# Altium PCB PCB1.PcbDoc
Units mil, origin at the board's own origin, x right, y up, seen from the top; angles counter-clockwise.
Board outline 2460.63 x 1000 mil, 4 copper layers (Top Layer, GND, POW, Bottom Layer), stack 30.634 mil thick; 99 components, 71 nets, 311 pads, 135 vias.
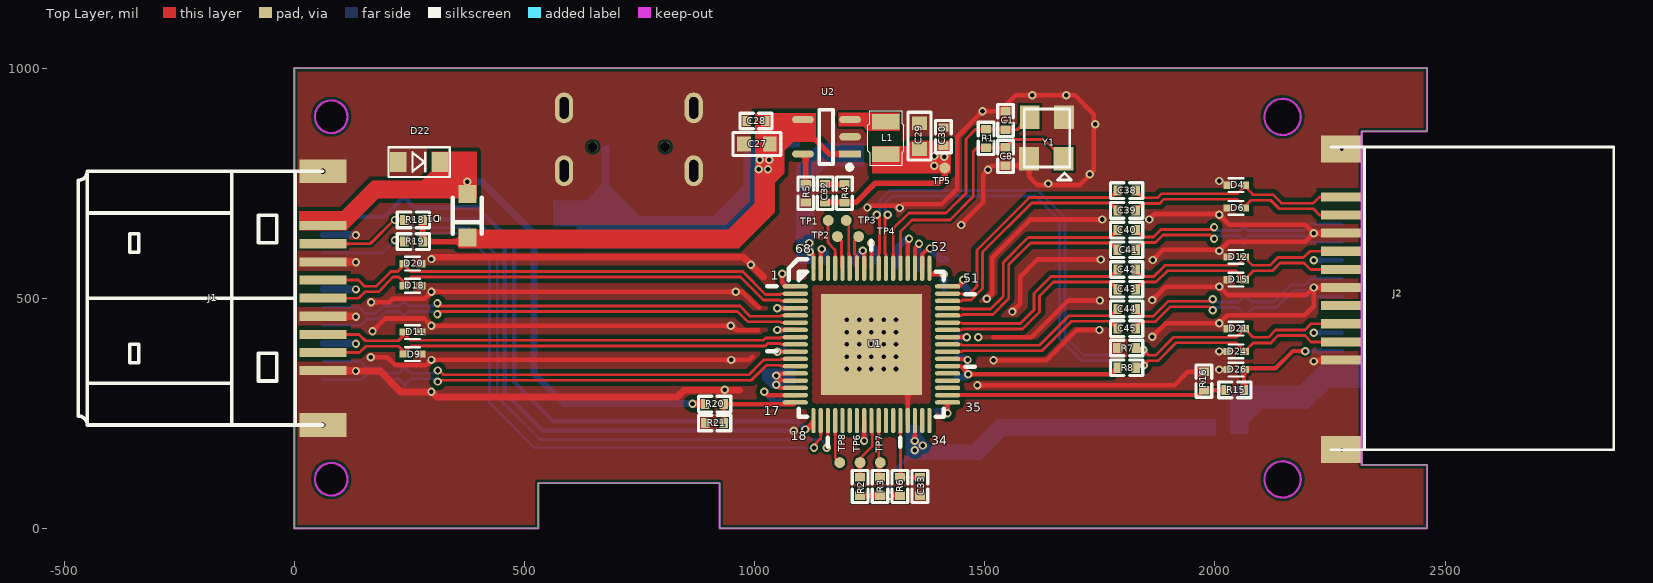
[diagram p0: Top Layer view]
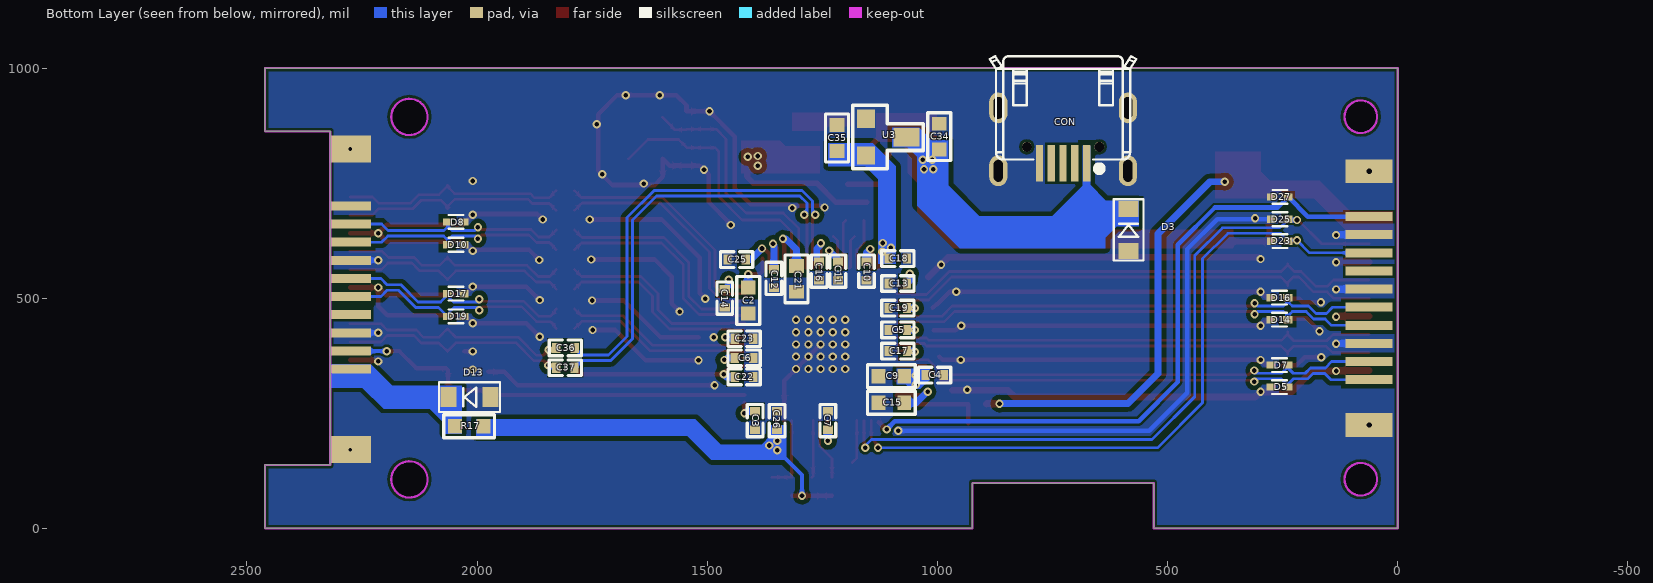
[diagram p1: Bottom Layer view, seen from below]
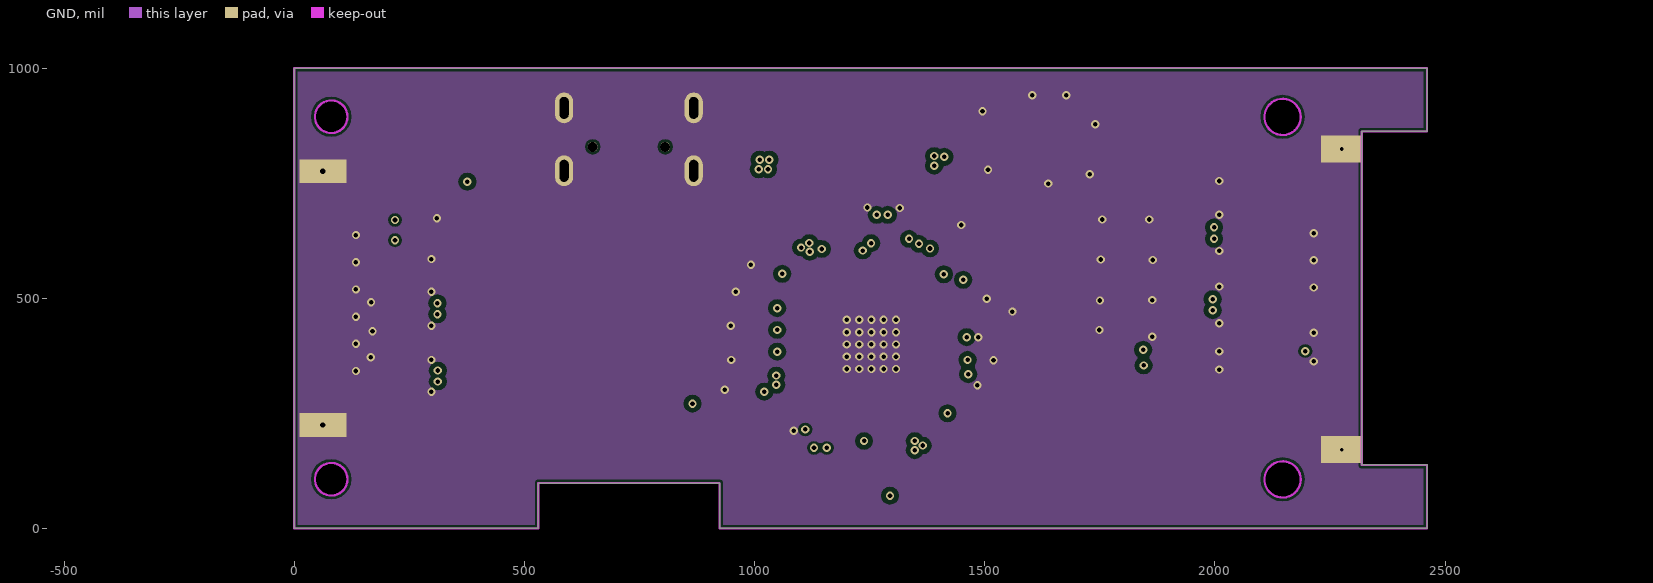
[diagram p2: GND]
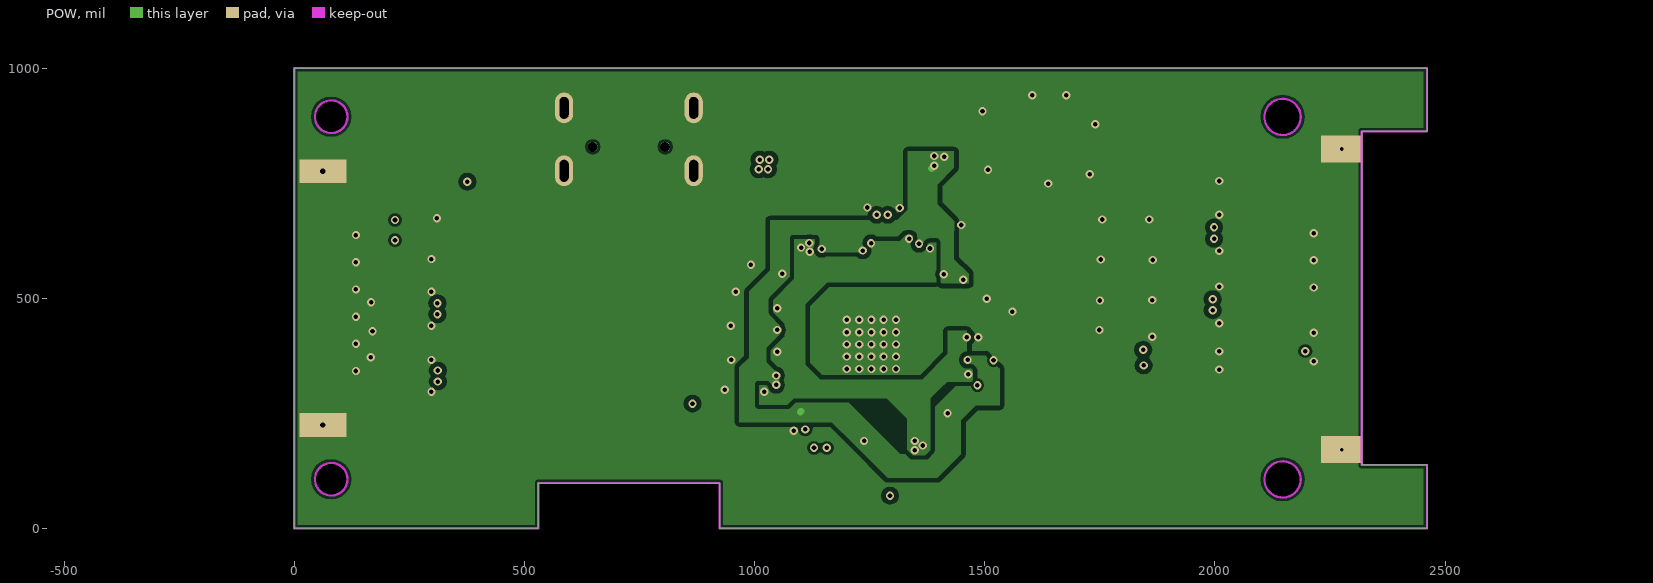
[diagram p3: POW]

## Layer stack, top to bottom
Top Solder: solder mask 0.4, Solder Resist, Dk 3.5
Top Layer: signal copper 1.4
Dielectric 1: core 10, FR-4, Dk 4.2
GND: signal copper 1.417
Dielectric 2: core 10, Dk 4.2
POW: signal copper 1.417
Dielectric 3: prepreg 5, Dk 4.2
Bottom Layer: signal copper 1.4
Bottom Solder: solder mask 0.4, Solder Resist, Dk 3.5

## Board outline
0,0 0,1000 2460.63,1000 2460.63,862.32 2318.9,862.32 2318.9,137.91 2460.63,137.91 2460.63,0 923.85,0 923.85,98.54 530.15,98.54 530.15,0
cut-out: 80.32,858.78 cw(c80.32,894.21) 44.88,894.21 cw(c80.32,894.21) 80.32,929.65 cw(c80.32,894.21) 115.75,894.21 cw(c80.32,894.21)
cut-out: 44.88,106.81 ccw(c80.32,106.81) 80.32,71.38 ccw(c80.32,106.81) 115.75,106.81 ccw(c80.32,106.81) 80.32,142.24 ccw(c80.32,106.81)
cut-out: 2107.48,106.42 ccw(c2146.85,106.42) 2146.85,67.05 ccw(c2146.85,106.42) 2186.22,106.42 ccw(c2146.85,106.42) 2146.85,145.79 ccw(c2146.85,106.42)
cut-out: 2107.48,893.82 ccw(c2146.85,893.82) 2146.85,854.45 ccw(c2146.85,893.82) 2186.22,893.82 ccw(c2146.85,893.82) 2146.85,933.19 ccw(c2146.85,893.82)

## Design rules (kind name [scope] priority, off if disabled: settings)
Clearance Clearance_3 [InComponentClass('New Class') vs InPolygon] p1: gap=5.5 except(10: SMDPad-Poly)
Clearance Clearance_2 [InNetClass('POW') vs InPolygon] p2: gap=5.5 except(10: Arc-Poly Track-Poly SMDPad-Poly THPad-Poly Via-Poly Fill-Poly Poly-Poly Poly-Region)
Clearance Clearance_1 [InNetClass('DIFF') vs InPolygon] p3: gap=5.5 except(10: Arc-Poly Track-Poly SMDPad-Poly THPad-Poly Via-Poly Fill-Poly Poly-Poly)
Clearance [All] p4: gap=5.5
DiffPairsRouting DiffPair_DiffPairsRouting [All] p1: maxlimit=6 minlimit=6 mostfreqgap=6 toplayer_minwidth=6 toplayer_maxwidth=6 toplayer_prefwidth=6 midlayer1_minwidth=6 midlayer1_maxwidth=6 midlayer1_prefwidth=6 midlayer2_minwidth=6 midlayer2_maxwidth=6 midlayer2_prefwidth=6 bottomlayer_minwidth=6 bottomlayer_maxwidth=6 bottomlayer_prefwidth=6 maxuncoupledlength=500
DiffPairsRouting [All] p2: maxlimit=10 minlimit=10 mostfreqgap=10 toplayer_minwidth=15 toplayer_maxwidth=15 toplayer_prefwidth=15 midlayer1_minwidth=15 midlayer1_maxwidth=15 midlayer1_prefwidth=15 midlayer2_minwidth=15 midlayer2_maxwidth=15 midlayer2_prefwidth=15 bottomlayer_minwidth=15 bottomlayer_maxwidth=15 bottomlayer_prefwidth=15 maxuncoupledlength=500
HoleSize [All] p1: absolutevalues=TRUE maxlimit=300 minlimit=1 maxpercent=80.000 minpercent=20.000
HoleToHoleClearance [All] p1: gap=6 allowstackedmicrovias=TRUE
MatchedLengths DiffPair_MatchedLengths [All] p1: tolerance=1000 checknetsindiffpair=FALSE checkdiffpairvsdiffpair=TRUE checkxsignals=TRUE checkothers=TRUE
MinimumSolderMaskSliver [All] p1: minsoldermaskwidth=5
PolygonConnect [All] p1: connectstyle=Direct reliefconductorwidth=10 reliefentries=4 polygonreliefangle="90 Angle" airgapwidth=10
RoutingVias [All] p1: holewidth=10 width=18 viastyle="Through Hole" minholewidth=8 minwidth=16 maxholewidth=10 maxwidth=18
SilkToSilkClearance [All] p1: silktosilkclearance=0
SilkToSolderMaskClearance [IsPad] p1: minsilkscreentomaskgap=0 clearancetoexposedcopper=TRUE
SolderMaskExpansion [All] p1: expansion=0
Width [All] p1: maxlimit=30 minlimit=6 preferedwidth=15
24 further rules are at their usual default settings.

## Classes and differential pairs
net class DIFF: DP_AUX_N DP_AUX_P DP_TX0_N DP_TX0_P DP_TX1_N DP_TX1_P DP_TX2_N DP_TX2_P DP_TX3_N DP_TX3_P DPTX0_N DPTX0_N_O DPTX0_P DPTX0_P_O DPTX1_N DPTX1_N_O DPTX1_P DPTX1_P_O DPTX2_N DPTX2_N_O DPTX2_P DPTX2_P_O DPTX3_N DPTX3_N_O DPTX3_P DPTX3_P_O DPTX_AUX_N DPTX_AUX_N_O DPTX_AUX_P DPTX_AUX_P_O HDMI_CK_N HDMI_CK_N_O HDMI_CK_P HDMI_CK_P_O HDMI_D0_N HDMI_D0_N_O HDMI_D0_P HDMI_D0_P_O HDMI_D1_N HDMI_D1_N_O HDMI_D1_P HDMI_D1_P_O HDMI_D2_N HDMI_D2_N_O HDMI_D2_P HDMI_D2_P_O
net class POW: 5V DP_POWER DVDD12 DVDD33 HDMI_5V USB5V
component class "New Class": U1 U2 U3
differential pair D_HDMI_D2: +HDMI_D2_P -HDMI_D2_N
differential pair D_HDMI_D2_O: +HDMI_D2_P_O -HDMI_D2_N_O
differential pair D_HDMI_D1: +HDMI_D1_P -HDMI_D1_N
differential pair D_HDMI_D1_O: +HDMI_D1_P_O -HDMI_D1_N_O
differential pair D_HDMI_D0: +HDMI_D0_P -HDMI_D0_N
differential pair D_HDMI_D0_O: +HDMI_D0_P_O -HDMI_D0_N_O
differential pair D_HDMI_CK: +HDMI_CK_P -HDMI_CK_N
differential pair D_HDMI_CK_O: +HDMI_CK_P_O -HDMI_CK_N_O
differential pair D_DPTX_AUX: +DPTX_AUX_P -DPTX_AUX_N
differential pair D_DPTX_AUX_O: +DPTX_AUX_P_O -DPTX_AUX_N_O
differential pair D_DPTX3: +DPTX3_P -DPTX3_N
differential pair D_DPTX3_O: +DPTX3_P_O -DPTX3_N_O
differential pair D_DPTX2: +DPTX2_P -DPTX2_N
differential pair D_DPTX2_O: +DPTX2_P_O -DPTX2_N_O
differential pair D_DPTX1: +DPTX1_P -DPTX1_N
differential pair D_DPTX1_O: +DPTX1_P_O -DPTX1_N_O
differential pair D_DPTX0: +DPTX0_P -DPTX0_N
differential pair D_DPTX0_O: +DPTX0_P_O -DPTX0_N_O
differential pair D_DP_TX3: +DP_TX3_P -DP_TX3_N
differential pair D_DP_TX2: +DP_TX2_P -DP_TX2_N
differential pair D_DP_TX1: +DP_TX1_P -DP_TX1_N
differential pair D_DP_TX0: +DP_TX0_P -DP_TX0_N
differential pair D_DP_AUX: +DP_AUX_P -DP_AUX_N

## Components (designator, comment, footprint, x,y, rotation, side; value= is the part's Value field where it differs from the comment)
C1 "18pF" "0402/1005 C2"#1 1545,886 r90 top
C2 "4.7uF" "0603/1608 C2" 1411,495 r90 bottom
C3 "0.1uF" "0402/1005 C2"#2 1396,234.29 r90 bottom
C4 "0.1uF" "0402/1005 C2"#2 1006,333 r0 bottom
C5 "0.1uF" "0402/1005 C2"#2 1086,431.14 r180 bottom
C6 "0.1uF" "0402/1005 C2"#2 1420,370.5 r0 bottom
C7 "0.1uF" "0402/1005 C2"#2 1238.01,234.29 r270 bottom
C8 "18pF" "0402/1005 C2"#1 1545,808 r270 top
C9 "4.7uF" "0603/1608 C2" 1100,330.65 r180 bottom
C10 "0.1uF" "0402/1005 C2"#2 1154,559 r90 bottom
C11 "0.1uF" "0402/1005 C2"#2 1216,559 r90 bottom
C12 "0.1uF" "0402/1005 C2"#2 1355,543 r90 bottom
C13 "0.1uF" "0402/1005 C2"#2 1086,532 r180 bottom
C14 "0.1uF" "0402/1005 C2"#2 1462,500 r90 bottom
C15 "4.7uF" "0603/1608 C2" 1100,273 r180 bottom
C16 "0.1uF" "0402/1005 C2"#2 1257,559 r90 bottom
C17 "0.1uF" "0402/1005 C2"#2 1086,385 r180 bottom
C18 "0.1uF" "0402/1005 C2"#2 1086,586 r0 bottom
C19 "0.1uF" "0402/1005 C2"#2 1086,478.39 r180 bottom
C21 "4.7uF" "0603/1608 C2" 1306,542 r90 bottom
C22 "0.1uF" "0402/1005 C2"#2 1420,329 r0 bottom
C23 "0.1uF" "0402/1005 C2"#2 1420,412 r0 bottom
C25 "0.1uF" "0402/1005 C2"#2 1436,584 r180 bottom
C26 "0.1uF" "0402/1005 C2"#2 1348.24,234.29 r270 bottom
C27 "10uF/16V" "0603/1608 C2" 1005,835 r180 top
C28 "0.1uF" "0402/1005 C2"#1 1003,885 r180 top
C29 "10uF/6.3V" "0603/1608 C2" 1358,852 r90 top
C30 "0.1uF" "0402/1005 C2"#1 1410,851 r90 top
C32 "22pF" "0402/1005 C2"#1 1153,728 r90 top
C33 "0.1uF" "0402/1005 C2"#1 1359,91 r90 top
C34 "10uF" "0603/1608 C2" 996,851 r90 bottom
C35 "10uF" "0603/1608 C2" 1218,848 r90 bottom
C36 "0.1uF" "0402/1005 C2"#2 1808,392 r180 bottom
C37 "0.1uF" "0402/1005 C2"#2 1808,349 r180 bottom
C38 "0.1uF" "0402/1005 C2"#1 1808,733.67 r180 top
C39 "0.1uF" "0402/1005 C2"#1 1808,690.85 r180 top
C40 "0.1uF" "0402/1005 C2"#1 1808,648.04 r180 top
C41 "0.1uF" "0402/1005 C2"#1 1808,605.22 r180 top
C42 "0.1uF" "0402/1005 C2"#1 1808,562.41 r180 top
C43 "0.1uF" "0402/1005 C2"#1 1808,519.59 r180 top
C44 "0.1uF" "0402/1005 C2"#1 1808,476.78 r180 top
C45 "0.1uF" "0402/1005 C2"#1 1808,433.96 r180 top
CON "MICROUSB" USB-MF-S1-180 727,1025.59 r180 bottom
D1 "B5819WS" 5819 375,680 r270 top
D3 "D22V0S1U2WS" SOD-323 585,647 r90 bottom
D4 "Diode 18TQ045" SOD-923_L0.8-W0.6-LS1.0-BI 2046,745.6 r180 top
D5 "Diode 18TQ045" SOD-923_L0.8-W0.6-LS1.0-BI 257,307 r0 bottom
D6 "Diode 18TQ045" SOD-923_L0.8-W0.6-LS1.0-BI 2046,696.14 r180 top
D7 "Diode 18TQ045" SOD-923_L0.8-W0.6-LS1.0-BI 257,354.86 r0 bottom
D8 "Diode 18TQ045" SOD-923_L0.8-W0.6-LS1.0-BI 2046,665.68 r180 bottom
D9 "Diode 18TQ045" SOD-923_L0.8-W0.6-LS1.0-BI 257,378.71 r0 top
D10 "Diode 18TQ045" SOD-923_L0.8-W0.6-LS1.0-BI 2046,616.22 r180 bottom
D11 "Diode 18TQ045" SOD-923_L0.8-W0.6-LS1.0-BI 257,426.57 r0 top
D12 "Diode 18TQ045" SOD-923_L0.8-W0.6-LS1.0-BI 2046,589.76 r180 top
D13 "D22V0S1U2WS" SOD-323 2015,285 r0 bottom
D14 "Diode 18TQ045" SOD-923_L0.8-W0.6-LS1.0-BI 257,453.43 r0 bottom
D15 "Diode 18TQ045" SOD-923_L0.8-W0.6-LS1.0-BI 2046,540.3 r180 top
D16 "Diode 18TQ045" SOD-923_L0.8-W0.6-LS1.0-BI 257,501.29 r0 bottom
D17 "Diode 18TQ045" SOD-923_L0.8-W0.6-LS1.0-BI 2046,509.84 r180 bottom
D18 "Diode 18TQ045" SOD-923_L0.8-W0.6-LS1.0-BI 257,527.14 r0 top
D19 "Diode 18TQ045" SOD-923_L0.8-W0.6-LS1.0-BI 2046,460.38 r180 bottom
D20 "Diode 18TQ045" SOD-923_L0.8-W0.6-LS1.0-BI 257,575 r0 top
D21 "Diode 18TQ045" SOD-923_L0.8-W0.6-LS1.0-BI 2046,433.92 r180 top
D22 "D22V0S1U2WS" SOD-323 270,796 r0 top
D23 "Diode 18TQ045" SOD-923_L0.8-W0.6-LS1.0-BI 256,624 r0 bottom
D24 "Diode 18TQ045" SOD-923_L0.8-W0.6-LS1.0-BI 2046,384.46 r180 top
D25 "Diode 18TQ045" SOD-923_L0.8-W0.6-LS1.0-BI 256,671.5 r0 bottom
D26 "Diode 18TQ045" SOD-923_L0.8-W0.6-LS1.0-BI 2046,345 r180 top
D27 "Diode 18TQ045" SOD-923_L0.8-W0.6-LS1.0-BI 256,720 r0 bottom
J1 "HDMI_19_F" HDMI-G 62.99,498.89 r90 top
J2 "DP_CONN_SOURCE" DP-20-J 2866.14,499.88 r90 top
L1 "10uH" SWPA252012S 1285,848 r270 top
R1 "1M" "0402/1005 R2" 1503,847 r270 top
R2 "10K" "0402/1005 R2" 1229,91 r90 top
R3 "10K" "0402/1005 R2" 1272.33,91 r90 top
R4 "100k" "0402/1005 R2" 1195,728 r270 top
R5 "100k" "0402/1005 R2" 1111,728 r90 top
R6 "10K" "0402/1005 R2" 1315.67,91 r90 top
R7 "100K" "0402/1005 R2" 1808,391.84 r180 top
R8 "100K" "0402/1005 R2" 1808,348.84 r180 top
R15 "1k" "0402/1005 R2" 2043,301 r0 top
R16 "100K" "0402/1005 R2" 1976,320 r90 top
R17 "NC/0R" "0603/1608 R3" 2017,222 r180 bottom
R18 "47K" "0402/1005 R2" 259,670 r0 top
R19 "47K" "0402/1005 R2" 259,623 r0 top
R20 "100K" "0402/1005 R2" 913,270 r0 top
R21 "1M" "0402/1005 R2" 913,229 r180 top
TP1 "TEST_POINT" PAD 1160,669 r90 top
TP2 "TEST_POINT" PAD 1180,634 r90 top
TP3 "TEST_POINT" PAD 1199,669 r90 top
TP4 "TEST_POINT" PAD 1226,634 r90 top
TP5 "TEST_POINT" PAD 1413,783 r90 top
TP6 "TEST_POINT" PAD 1229,143 r90 top
TP7 "TEST_POINT" PAD 1273,143 r90 top
TP8 "TEST_POINT" PAD 1185,143 r90 top
U1 "CS5801" QFN68 1253.76,399.65 r0 top
U2 "SY8088" SOT23-5L 1167,852 r180 top
U3 "NA/LP3986-33B3F" SOT-123-B 1155,890 r270 bottom
Y1 "27MHZ" SMD3225 1635,848 r90 top

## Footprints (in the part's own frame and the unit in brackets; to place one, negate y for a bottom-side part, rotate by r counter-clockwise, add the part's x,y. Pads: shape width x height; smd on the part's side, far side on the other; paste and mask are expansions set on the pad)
"0402/1005 C2"#1 [mil]
  rect 18x22 smd mask+2: 1(-20,0)
  rect 18x22 smd mask+2.76: 2(20,0)
  silkscreen extent -35,-17 35,17, body extent -29,-11 29,11, height 20
"0402/1005 C2"#2 [mil]
  rect 18x22 smd mask+2: 1(-20,0) 2(20,0)
  silkscreen extent -35,-17 35,17, body extent -29,-11 29,11, height 20
"0402/1005 R2" [mil]
  rect 18x22 smd mask+2: 1(-20,0)
  rect 18x22 smd mask+2.76: 2(20,0)
  silkscreen extent -35,-17 35,17, body extent -29,-10 29,10, height 12
"0603/1608 C2" [mil]
  rect 30x32 smd mask+4: 1(-28,0)
  rect 30x32 smd: 2(28,0)
  silkscreen extent -52,-25 52,25, body extent -43,-16 43,16, height 31
"0603/1608 R3" [mil]
  rect 30x32 smd: 1(-31,0)
  rect 30x32 smd mask+4: 2(31,0)
  silkscreen extent -55,-25 55,25, body extent -46,-16 46,16, height 16
5819 [mm]
  rect 1x1 smd: 1(-1.175,0.025) 2(1.225,0.025)
  silkscreen extent -0.97,-0.77 1.03,0.83, body extent -1.27,-0.65 1.33,0.7, height 1.1
DP-20-J [mm]
  rect 0.5x2.3 smd: 1(5.593,15) 3(4.593,15) 5(3.593,15) 7(2.593,15) 9(1.593,15) 11(0.593,15) 13(-0.407,15) 15(-1.407,15) 17(-2.407,15) 19(-3.407,15)
  rect 0.5x2.3 smd far side: 2(5.093,15) 4(4.093,15) 6(3.093,15) 8(2.093,15) 10(1.093,15) 12(0.093,15) 14(-0.907,15) 16(-1.907,15) 18(-2.907,15) 20(-3.907,15)
  rect 1.5x2.3 hole 0.2: A(8.235,15) B(-8.352,15)
  silkscreen extent -8.35,0 8.35,15.6
HDMI-G [mm]
  rect 0.5x2.6 smd far side: 1(-4.468,0.016) 3(-3.468,0.016) 5(-2.468,0.016) 7(-1.468,0.016) 9(-0.468,0.016) 11(0.532,0.016) 13(1.532,0.016) 15(2.532,0.016) 17(3.532,0.016) 19(4.532,0.016)
  rect 0.5x2.6 smd: 2(-3.968,0.016) 4(-2.968,0.016) 6(-1.968,0.016) 8(-0.968,0.016) 10(0.032,0.016) 12(1.032,0.016) 14(2.032,0.016) 16(3.032,0.016) 18(4.032,0.016)
  rect 1.3x2.6 hole 0.3: 20(7.032,0.016) 21(-6.968,0.016)
  silkscreen extent -6.97,0.02 7.03,13.52
PAD [mm] "TEST_PAD"
  round 0.6 smd: 1(0,0)
QFN68 [mm]
  oval 1.4x0.24 smd mask+0.05: 1(-4.2,3.2) 2(-4.2,2.8) 3(-4.2,2.4) 4(-4.2,2) 5(-4.2,1.6) 6(-4.2,1.2) 7(-4.2,0.8) 8(-4.2,0.4) 9(-4.2,0) 10(-4.2,-0.4) 11(-4.2,-0.8) 12(-4.2,-1.2) 13(-4.2,-1.6) 14(-4.2,-2) 15(-4.2,-2.4) 16(-4.2,-2.8) 17(-4.2,-3.2) 35(4.2,-3.2) 36(4.2,-2.8) 37(4.2,-2.4) 38(4.2,-2) 39(4.2,-1.6) 40(4.2,-1.2) 41(4.2,-0.8) 42(4.2,-0.4) 43(4.2,0) 44(4.2,0.4) 45(4.2,0.8) 46(4.2,1.2) 47(4.2,1.6) 48(4.2,2) 49(4.2,2.4) 50(4.2,2.8) 51(4.2,3.2)
  oval 0.24x1.4 smd mask+0.05: 18(-3.2,-4.2) 19(-2.8,-4.2) 20(-2.4,-4.2) 21(-2,-4.2) 22(-1.6,-4.2) 23(-1.2,-4.2) 24(-0.8,-4.2) 25(-0.4,-4.2) 26(0,-4.2) 27(0.4,-4.2) 28(0.8,-4.2) 29(1.2,-4.2) 30(1.6,-4.2) 31(2,-4.2) 32(2.4,-4.2) 33(2.8,-4.2) 34(3.2,-4.2) 52(3.2,4.2) 53(2.8,4.2) 54(2.4,4.2) 55(2,4.2) 56(1.6,4.2) 57(1.2,4.2) 58(0.8,4.2) 59(0.4,4.2) 60(0,4.2) 61(-0.4,4.2) 62(-0.8,4.2) 63(-1.2,4.2) 64(-1.6,4.2) 65(-2,4.2) 66(-2.4,4.2) 67(-2.8,4.2) 68(-3.2,4.2)
  rect 5.588x5.588 smd paste-1.5 mask+0.05: 69(0,0)
  silkscreen extent -5.74,-5.65 5.69,5.72, body extent -4.02,-3.94 4.02,4.1, height 0.84
SMD3225 [mm]
  rect 1.3x1.1 smd: 1(-1.15,-0.92) 2(1.15,-0.95) 3(1.15,0.95) 4(-1.15,0.98)
  silkscreen extent -2.31,-1.35 1.6,1.25
SOD-323 [mm]
  rect 0.9x1.1 smd: 1(-1.125,-0.003) 2(1.186,-0.003)
  silkscreen extent -1.65,-0.83 1.72,0.82
SOD-923_L0.8-W0.6-LS1.0-BI [mm]
  rect 0.5x0.4 smd: 1(-0.457,0) 2(0.457,0)
  silkscreen extent -0.41,-0.38 0.41,0.38
SOT23-5L [mm]
  rect 1.2x0.4 smd paste+0 mask+0.102: 1(-1.025,0.986)
  oval 1.2x0.4 smd paste+0 mask+0.102: 2(-1.025,0.036) 3(-1.025,-0.914) 4(1.575,-0.914) 5(1.575,0.986)
  silkscreen extent -1.13,-1.46 0.67,1.84, body extent -1.16,-1.41 1.64,1.49, height 1.2
SOT-123-B [mil]
  rect 40x40 smd: 1(0,0) 2(80,0)
  rect 40x55.75 smd: 3(40,88)
  silkscreen extent -29,-29 109,124
SWPA252012S [mm]
  rect 0.85x1.5 smd mask+0.051: 1(-0.9,0) 2(0.9,0)
  silkscreen extent -1.5,-1 1.5,1
USB-MF-S1-180 [mm]
  rect 0.4x2 smd: 1(1.3,-5.9) 2(0.65,-5.9) 3(0,-5.9) 4(-0.65,-5.9) 5(-1.3,-5.9)
  oval 1x1.7 hole 0.5 slot 1.2 at 90 deg: 6(-3.575,-2.85) 7(3.575,-2.85) 8(-3.575,-6.32) 9(3.575,-6.32)
  round 0.55 hole 0.55: 10(-2,-5) 11(2,-5)
  silkscreen extent -4.05,-6.3 4.05,0

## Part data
C1 C2 C3 C4 C5 C6 C7 C8 C9 C10 C11 C12 C13 C14 C15 C16 C17 C18 C19 C21 C22 C23 C25 C26 C27 C28 C29 C30 C32 C33 C34 C35 C36 C37 C38 C39 C40 C41 C42 C43 C44 C45: library part "CAP NP"
D1: library part B5819WS_C22624
D3 D13 D22: library part "Diode 18TQ045", "Schottky Rectifier"
D4 D5 D6 D7 D8 D9 D10 D11 D12 D14 D15 D16 D17 D18 D19 D20 D21 D23 D24 D25 D26 D27: "Schottky Rectifier"
J1: library part HDMI_F
J2: library part DP_CONN_SOURCE_0_1
R1 R2 R3 R4 R5 R6 R15 R17 R20 R21: library part R0603
R7 R8 R16: library part "0603 47K Ohm 5%"
R18 R19: library part R
U2: library part AP3406K-ADJTRG1_0
U3: library part LDO_3Pin
Y1: library part CRYSTAL_SMD

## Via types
v1: diameter 18, hole 10, Top Layer to Bottom Layer, tented both sides, 135 vias

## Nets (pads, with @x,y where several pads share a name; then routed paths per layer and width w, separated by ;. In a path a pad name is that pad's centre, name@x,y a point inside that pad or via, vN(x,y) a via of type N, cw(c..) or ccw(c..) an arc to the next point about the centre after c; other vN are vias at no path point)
5V: C27.1 C28.1 C34.1 CON.1 D1.2 D3.2 R18.2 R19.2 U2.1 U2.4 U3.3 | length 293.1
  Top Layer w12: R18.2 R19.2 376,623 D1.2@376,628.76 ; U2.4 1105,871 1162.8,813.2 U2.1
  other v1: 1009,780 1029,780 1011,801 1032,801
CFG_SCL: R3.2 TP7.1 U1.27 | length 124.5
  Top Layer w6: U1.27 1269.5,143 1269.5,113.83 R3.2
CFG_SDA: R2.2 TP6.1 U1.26 | length 135.2
  Top Layer w6: R2.2 TP6.1 1229,152 1255.76,178.76 1255.76,232.28 U1.26
DP_AUX_N: C37.2 U1.58 | length 963.9
  Top Layer w6: U1.58 1285.25,595.56 1283.38,597.43 1283.38,675 v1(1289.38,681)
  Bottom Layer w6: v1(1289.38,681) 1283.38,687 1283.38,706.41 1298.97,722 1610.03,722 1662,670.03 1662,412 1709.5,364.5 1772.5,364.5 C37.2
DP_AUX_P: C36.2 U1.59 | length 983.8
  Top Layer w6: v1(1265.38,681) 1271.38,675 1271.38,597.43 1269.5,595.56 U1.59
  Bottom Layer w6: v1(1265.38,681) 1271.38,687 1271.38,711.38 1294,734 1615,734 1674,675 1674,416.97 1714.47,376.5 1772.5,376.5 C36.2
DP_CONN_HPD: D26.1 J2.18 R15.2 | length 272.8
  Top Layer w9: R15.2 2063,344 D26.1 2067,348 2132,348 2169,385 v1(2196,385)
  Bottom Layer w9: v1(2196,385) 2275.14,385 J2.18
DP_POWER: D13.2 J2.20 R17.1
DP_TX0_N: C39.2 U1.49 | length 510
  Top Layer w6: U1.49 1449.67,494.13 1451.54,496.01 1469.97,496.01 1495,521.04 1495,600.03 1601.97,707 1771.85,707 C39.2
DP_TX0_P: C38.2 U1.50 | length 509.4
  Top Layer w6: U1.50 1449.67,509.88 1451.54,508.01 1465,508.01 1483,526.01 1483,605 1597,719 1773.33,719 C38.2
DP_TX1_N: C41.2 U1.47 | length 483.5
  Top Layer w6: U1.47 1449.67,462.64 1451.54,464.51 1517.51,464.51 1552,499 1552,573 1599,620 1773.22,620 C41.2
DP_TX1_P: C40.2 U1.48 | length 484.1
  Top Layer w6: U1.48 1449.67,478.39 1451.54,476.51 1512.54,476.51 1540,503.97 1540,577.97 1594.03,632 1771.96,632 C40.2
DP_TX2_N: C43.2 U1.45 | length 438.8
  Top Layer w6: U1.45 1449.67,431.14 1451.54,433.02 1582.02,433.02 1619,470 1619,505 1649,535 1772.59,535 C43.2
DP_TX2_P: C42.2 U1.46 | length 438.8
  Top Layer w6: U1.46 1449.67,446.89 1451.54,445.02 1577.05,445.02 1607,474.97 1607,509.97 1644.03,547 1772.59,547 C42.2
DP_TX3_N: C45.2 U1.42 | length 402.9
  Top Layer w6: U1.42 1449.67,383.9 1451.54,385.77 1623.74,385.77 1687.97,450 1771.96,450 C45.2
DP_TX3_P: C44.2 U1.43 | length 402.4
  Top Layer w6: U1.43 1449.67,399.65 1451.54,397.77 1618.77,397.77 1683,462 1773.22,462 C44.2
DP_TX_HPD: R15.1 R16.1 U1.36 | length 608.7
  Top Layer w9: U1.36 1965.41,289.41 R16.1 2022,300 R15.1
DPTX0_N: C39.1 D6.1 J2.3 | length 495.3
  Top Layer w6: C39.1 1843.15,706 1880,706 1889.09,715.09 2047.91,715.09 2064,699 D6.1 ; D6.1@2061,697.14 2063,695.14 2064,694.14 2065,695.14 2067,697.14 2067,702 2077.87,712.87 2121.13,712.87 2139.59,694.41 2213.63,694.41 2227.32,680.72 J2.3
DPTX0_N_O: 
DPTX0_P: C38.1 D4.1 J2.1 | length 488.7
  Top Layer w6: C38.1 1843.67,718 1875.03,718 1884.12,727.09 2049.09,727.09 2061,739 2061,742.6 D4.1 ; D4.1@2064,743.6 2082.73,724.87 2126.1,724.87 2144.56,706.41 2213.63,706.41 2227.32,720.09 J2.1
DPTX0_P_O: 
DPTX1_N: C41.1 D10.1 J2.6 | length 500
  Top Layer w6: C41.1 1831,608.22 1831,609 1843,621 1871,621 1887.27,637.27 1989.73,637.27 v1(1998,629)
  Bottom Layer w6: v1(1998,629) 2003.95,634.95 2054,634.95 2061,627.95 2061,619.22 D10.1 2064,627 2072.35,635.35 2193.65,635.35 2207.33,621.67 J2.6
DPTX1_N_O: 
DPTX1_P: C40.1 D8.1 J2.4 | length 497.8
  Top Layer w6: C40.1 1831,645.04 1843,633 1866.03,633 1882.3,649.27 1993.27,649.27 v1(1998,654)
  Bottom Layer w6: v1(1998,654) 2005.05,646.95 2054,646.95 2061,653.95 2061,662.68 D8.1 2064,655 2071.65,647.35 2193.35,647.35 2207.04,661.04 J2.4
DPTX1_P_O: 
DPTX2_N: C43.1 D15.1 J2.9 | length 493.8
  Top Layer w6: C43.1 1831,522.59 1831,524 1842,535 1872,535 1896.45,559.45 2045.55,559.45 2064,541 D15.1 2083.15,559.45 2124.45,559.45 2128.97,563.97 2141.3,576.3 2193.7,576.3 2207.39,562.61 J2.9
DPTX2_N_O: 
DPTX2_P: C42.1 D12.1 J2.7 | length 491.6
  Top Layer w6: C42.1 1831,559.41 1831,558 1842,547 1867.03,547 1891.48,571.45 2047.45,571.45 2064,588 D12.1 ; D12.1@2064,584.45 2068.55,584.45 2081.55,571.45 2119.48,571.45 2136.33,588.3 2192.3,588.3 2205.98,601.98 J2.7
DPTX2_P_O: 
DPTX3_N: C45.1 D19.1 J2.12 | length 513.9
  Top Layer w6: C45.1 1831,436.96 1831,440 1840,449 1871,449 1903.63,481.63 1987.37,481.63 v1(1995,474)
  Bottom Layer w6: v1@1994,480 1995,480 2050,480 2064,466 D19.1 2083.62,480 2133,480 2170.24,517.24 2195.19,517.24 2208.87,503.56 J2.12
DPTX3_N_O: 
DPTX3_P: C44.1 D17.1 J2.10 | length 510.2
  Top Layer w6: C44.1 1831,473.78 1831,470 1840,461 1866.03,461 1898.66,493.63 1990.63,493.63 v1(1995,498)
  Bottom Layer w6: v1@1994,492 1995,492 2051,492 2064,505 D17.1@2064,507 ; D17.1 D17.1@2064,507 ; J2.10 2208.87,542.93 2195.19,529.24 2165.27,529.24 2128.03,492 2079,492 D17.1@2064,507
DPTX3_P_O: 
DPTX_AUX_N: C37.1 D24.1 J2.17 R8.1 | length 498
  Top Layer w6: v1(1845,354) 1855,364 1876,364 1915.19,403.19 2045.81,403.19 2061,388 2061,387.46 D24.1 2067,387.46 2067.46,387.46 2083,403 2121,403 2136.82,418.82 2195.19,418.82 2208.87,405.13 J2.17
  Bottom Layer w6: C37.1 1840,349 v1(1845,354)
DPTX_AUX_N_O: 
DPTX_AUX_P: C36.1 D21.1 J2.15 R7.1 | length 481.1
  Top Layer w6: v1(1844,388) 1856,376 1871.03,376 1910.22,415.19 2046.19,415.19 2061,430 2061,430.92 D21.1 2067,430.92 2067.08,430.92 2083,415 2116.03,415 2131.85,430.82 2195.19,430.82 2208.87,444.5 J2.15
DPTX_AUX_P_O: 
DVDD12: C2.2 C3.2 C4.2 C5.2 C6.2 C7.2 C9.2 C10.2 C11.2 C12.2 C13.2 C14.2 C29.1 C30.1 C32.1 L1.2 R4.2 TP5.1 U1.1 U1.7 U1.13 U1.14 U1.15 U1.25 U1.35 U1.41 U1.51 U1.52 U1.54 U1.61 U1.67 | length 1174.5
  Top Layer w9: v1(1047,312) 1053.84,305.16 U1.15 ; v1(1060,553) 1060,534 1068.37,525.63 U1.1 ; U1.14 1058.09,320.91 v1(1047,332) 1051.65,336.65 U1.13 ; U1.67 v1@1143.52,607 ; v1@1238.01,190 U1.25 ; U1.54 1348.24,609.24 v1(1357,618) ; U1.52@1379.74,585.74 U1.52 1379.74,558.26 1386,552 v1(1411,552) ; v1(1419.11,250.11) U1.35 ; U1.41 1458.46,368.15 v1@1460.61,366 ; U1.51 1443.63,525.63 1453,535 v1(1453,540)
  Top Layer w10: v1(1048.91,431.14) U1.7 ; v1(1235.01,603.5) 1238.01,600.5 U1.61
  Top Layer w12: C32.1 R4.2 1220,708 1262,750 1400,750 1413,763 TP5.1
  POW w15: 1099.18,253 1100.68,254.5 ; v1@1384,782 v1(1390,788)
  Bottom Layer w15: v1(1048.91,431.14) C5.2 ; v1(1060,553) 1060,538 C13.2 ; v1(1146,607) 1154,599 C10.2 ; C11.2 1216,584.49 v1(1235.01,603.5) ; v1(1237.76,190) 1238.01,190.24 C7.2 ; C12.2 1355,616 v1(1357,618) ; C3.2 1414.93,254.29 v1(1419.11,250.11) ; C2.2 v1(1411,552) ; C6.2 1456.11,370.5 v1@1460.61,366 ; v1(1453,540) 1453,529 C14.2
  other v1: 1462.61,366 1412,807 1390,809
DVDD33: C15.2 C16.2 C17.2 C18.2 C19.2 C21.2 C22.2 C23.2 C25.2 C26.2 C35.1 R2.1 R3.1 R6.1 R8.2 R17.2 U1.4 U1.10 U1.16 U1.32 U1.40 U1.44 U1.53 U1.55 U1.60 U1.68 U3.2 | length 1340.7
  Top Layer w8: U1.60@1254,565 v1@1254,615.5
  Top Layer w9: v1(1120.05,600.98) 1127.77,593.26 U1.68 ; R2.1 R3.1 v1(1294,71) R6.1 ; v1@1348.24,190 U1.32 ; U1.53 1363.99,594.99 1379,610 v1@1381,612 ; U1.40 1447.73,352.4 1464,336.13 v1(1464,335) 1774.16,335 R8.2
  Top Layer w10: v1(1021,297) 1028.59,289.41 U1.16 ; v1(1048.91,383.9) U1.10 ; v1(1048.91,478.39) U1.4 ; U1.55 1332.5,626 v1(1335.5,629) ; U1.44 v1(1460.61,415.39)
  Bottom Layer w9: v1(1294,71) 1294,116 v1(1348,170)
  Bottom Layer w15: v1(1021,297) 1045,273 C15.2 ; v1(1048.91,383.9) 1050.01,385 C17.2 ; v1(1048.91,478.39) C19.2 ; v1@1254,615.5 1262,607.5 1262,584 C16.2 ; C21.2 1306,606 1329,629 v1(1335.5,629) ; v1(1381,608) 1405,584 C25.2 ; C22.2 1458,329 v1(1464,335) ; C23.2 1443.39,415.39 v1(1460.61,415.39)
  other v1: 1365,180 1348,190 1101,610 1119,620 1253,619.5
GND: C1.2 C2.1 C3.1 C4.1 C5.1 C6.1 C7.1 C8.2 C9.1 C10.1 C11.1 C12.1 C13.1 C14.1 C15.1 C16.1 C17.1 C18.1 C19.1 C21.1 C22.1 C23.1 C25.1 C26.1 C27.2 C28.2 C29.2 C30.2 C33.1 C34.2 C35.2 CON.5 CON.6 CON.7 CON.8 CON.9 D3.1 D4.2 D5.2 D6.2 D7.2 D8.2 D9.2 D10.2 D11.2 D12.2 D13.1 D14.2 D15.2 D16.2 D17.2 D18.2 D19.2 D20.2 D21.2 D22.1 D23.2 D24.2 D25.2 D26.2 D27.2 J1.2 J1.5 J1.8 J1.11 J1.14 J1.17 J1.20 J1.21 J2.2 J2.5 J2.8 J2.11 J2.16 J2.19 J2.A J2.B R5.1 R7.2 R16.2 R21.2 U1.31 U1.69 U2.2 U3.1 Y1.2 Y1.4 | length 10801
  Top Layer w10: v1(166,372) 202,372 220,354 286,354 v1(298,366) v1(949,366) 989,366 996,373 ; v1(167,491) 206,491 214,499 283,499 v1(298,514) v1(959,514) 973,514 1001,486 1003,486 1010,479 ; v1(170,428) 198,456 282,456 v1(298,440) v1(948,440) 951,440 961,430 1008,430 ; v1(1245,697) 1250,697 1254,701 1310,701 v1(1315,696) 1323,704 1406,704 1440,738 1440,851 v1(1495,906) C1.2 1545,919 1567,941 v1(1603,941) v1(1677,941) 1696,941 1737,900 1737,878 1737,777 1728.5,768.5 1706,746 1638,746 1614,746 1596.42,763.58 Y1.4 1581.69,788 C8.2 1516,788 v1(1507,779) 1497,769 1497,709 v1@1448.5,660.5 ; v1(1253.76,399.65) v1(1280.11,373.29) v1(1307.11,346.29) 1332.5,320.91 U1.31 ; v1(1484,311) 1912,311 1941,340 R16.2 ; v1(1504,499) 1516,511 1516,588 1599,671 v1(1755,671) ; 1518,415.39 1601.39,415.39 1681,495 v1(1750,495) ; v1(1519,365) 1634,365 1700,431 v1(1749,431) ; v1(1560,471) 1577,488 1577,547 1614,584 v1(1752,584) ; v1(1857,671) 1869,683 2007.54,683 v1(2009.4,681.14) 2030.54,660 2196,660 v1(2214.65,641.35) ; v1(1864,416) 1893.38,445.38 v1(2009.4,445.38) 2027.02,463 2195,463 2214.65,482.65 v1(2214.65,523.24) ; v1(1864,496) 1893.3,525.3 v1(2009.4,525.3) 2027.7,507 2198.4,507 v1(2214.65,523.24) ; v1(1865,583) 1887,605 2007.16,605 v1(2009.4,602.76) 2029.64,623 2196.29,623 v1(2214.65,641.35) ; v1(2009.4,345) D26.2 ; v1(2009.4,384.46) D24.2 ; v1@2214.65,365.76 J2.19 ; J2.11 v1(2214.65,523.24) ; J2.5 v1(2214.65,641.35)
  Top Layer w15: J1.2 v1@134,342.67 ; J1.8 v1@134,460.78 ; J1.14 v1@134,578.89 ; v1(134,341.89) 186.11,341.89 231.38,296.62 v1(298,296.62) 309.62,285 832,285 847,300 935,300 967,300 ; v1(298,585) 302,589 976,589 v1(992,573) 1019,546
  Bottom Layer w10: D25.2 310,671.5 392.5,671.5 457,607 457,295 540,212 v1(1085,212) ; v1(2214.65,424.82) J2.16 ; v1(2214.65,582.3) J2.8
  Bottom Layer w15: J1.5 v1@134,401.72 ; J1.11 v1@134,519.83 ; J1.17 v1@134,637.94
  other v1: 935,301 1200.4,346.29 1227.4,346.29 1253.76,346.29 1280.11,346.29 2214.65,362.76 1200.4,373.29 1227.4,373.29 1253.76,373.29 1307.11,373.29 1200.4,399.65 1227.4,399.65 1280.11,399.65 1307.11,399.65 134,400.94 1486,415.39 1200.4,426 1227.4,426 1253.76,426 1280.11,426 1307.11,426 1200.4,453 1227.4,453 1253.76,453 1280.11,453 1307.11,453 134,460 134,519.06 134,578.11 134,637.17 1449,659 310,674 1638,749 2009.4,754.6 1728,769 1740,878
GPIO10/SPI_CLK: TP2.1 U1.64 | length 73.5
  Top Layer w6: TP2.1 1188.74,625.26 1188.74,567.02 U1.64
GPIO11/SPI_CSN: TP3.1 U1.63 | length 107.1
  Top Layer w6: TP3.1 1204.49,663.51 1204.49,567.02 U1.63
GPIO12/SPI_SI: TP4.1 U1.62 | length 74.9
  Top Layer w6: U1.62 1220.24,567.02 1220.24,593.52 1217,596.76 1217,625 TP4.1
GPIO13/SPI_SO: TP1.1 U1.65 | length 110.9
  Top Layer w6: TP1.1 1159.19,668.19 1159.19,620.81 1175.02,604.98 U1.65
HDMI_5V: D1.1 D22.2 J1.18 R20.1 | length 895.1
  Top Layer w15: v1(865,271) 892,271 R20.1
  Bottom Layer w15: v1(376,753) 408,753 521,640 521,336 586,271 v1(865,271)
HDMI_CK_N: 
HDMI_CK_N_O: D20.1 J1.12 U1.2 | length 1081.1
  Top Layer w6: J1.12 139.48,539.52 153.17,525.83 177.86,525.83 209.84,557.81 224.81,557.81 D20.1@239,572 ; D20.1 D20.1@239,572 ; U1.2 1057.84,509.88 1055.96,508 1023.97,508 974.16,557.81 253.19,557.81 D20.1@239,572
HDMI_CK_P: 
HDMI_CK_P_O: D18.1 J1.10 U1.3 | length 1084.2
  Top Layer w6: J1.10 140.15,500.15 153.83,513.83 182.83,513.83 214.81,545.81 227,545.81 239,533.81 D18.1@239,530.81 ; D18.1 D18.1@239,530.81 ; U1.3 1057.84,494.13 1055.98,496 1019,496 969.19,545.81 254,545.81 D18.1@239,530.81
HDMI_D0_N: 
HDMI_D0_N_O: D16.1 J1.9 U1.5 | length 1075.9
  Top Layer w6: v1@311,483.14 967.86,483.14 990.24,460.76 1055.97,460.76 1057.84,462.64 U1.5
  Bottom Layer w6: J1.9 141.54,480.46 155.22,466.78 177.78,466.78 194,483 229,483 236,490 236,498.29 D16.1 242,498.29 242,489.36 248,483.36 305.36,483.36 v1(311,489)
HDMI_D0_P: 
HDMI_D0_P_O: D14.1 J1.7 U1.6 | length 1075.5
  Top Layer w6: v1@311,471.14 962.88,471.14 985.27,448.76 1055.97,448.76 1057.84,446.89 U1.6
  Bottom Layer w6: J1.7 144.09,441.09 157.78,454.78 182.75,454.78 198.97,471 229,471 236,464 236,456.43 D14.1 242,456.43 242,465.36 248,471.36 304.64,471.36 v1(311,465)
HDMI_D1_N: 
HDMI_D1_N_O: D11.1 J1.6 U1.8 | length 1050
  Top Layer w6: J1.6 140.59,421.41 154.28,407.72 226,407.72 D11.1@239,420.72 ; D11.1 239,422.23 252.76,408.48 1018.51,408.48 1023.55,413.52 1055.97,413.52 1057.84,415.39 U1.8
HDMI_D1_P: 
HDMI_D1_P_O: D9.1 J1.4 U1.9 | length 1050.1
  Top Layer w6: J1.4 142.04,382.04 155.72,395.72 226.28,395.72 239,383 D9.1@239,382 ; D9.1 D9.1@239,382 ; U1.9 1057.84,399.65 1055.97,401.52 1028.52,401.52 1023.48,396.48 253.48,396.48 D9.1@239,382
HDMI_D2_N: 
HDMI_D2_N_O: D7.1 J1.3 U1.11 | length 1075.1
  Top Layer w6: v1(312,342.93) 315.07,342.93 324.19,333.81 987.81,333.81 1012,358 ; 1012.03,358.03 1020.28,366.28 1055.97,366.28 1057.84,368.15 U1.11
  Bottom Layer w6: J1.3 143.65,362.35 157.33,348.67 189.33,348.67 201.07,336.93 227,336.93 239,348.93 D7.1 242,351.86 242,347.93 253,336.93 v1@312,336.93
HDMI_D2_P: 
HDMI_D2_P_O: D5.1 J1.1 U1.12 | length 1072.6
  Top Layer w6: v1(312,318.93) 314.88,321.81 992.78,321.81 1025.25,354.28 1055.97,354.28 1057.84,352.4 U1.12
  Bottom Layer w6: J1.1 144.98,322.98 158.67,336.67 184.36,336.67 196.1,324.93 227.07,324.93 239,313 D5.1 242,310 242,313.93 253,324.93 v1@312,324.93
HDMI_HPD: D27.1 J1.19 U1.18 | length 1473.6
  Top Layer w10: v1(1110,215) 1111.8,215 U1.18@1127.8,231
  Bottom Layer w10: J1.19 195.31,677.31 D27.1 261,697 397,697 478,616 478,318 563,233 1092.28,233 1110,215.28 v1(1110,215)
HDMI_SCL: D23.1 J1.15 R19.1 U1.19 | length 1537.8
  Top Layer w6: v1(219,626) 236,626 R19.1 ; v1(1129,175) 1129,181 1143.52,195.52 U1.19
  Bottom Layer w6: J1.15 191.57,598.57 v1(219,626) 228,626 ; D23.1 254.87,640.87 369.13,640.87 424,586 424,273 522,175 v1(1129,175)
HDMI_SDA: D25.1 J1.16 R18.1 U1.20 | length 1580.7
  Top Layer w6: J1.16 165.26,618.26 217,670 v1(219,670) R18.1 ; v1(1157,175) 1159.27,177.27 U1.20
  Bottom Layer w6: v1(219,670) 236.5,670 D25.1 256.63,652.87 381.13,652.87 441,593 441,286 534,193 1143,193 v1@1157,179
HDMI_SRC_DET: R20.2 R21.1 U1.17 | length 197.9
  Top Layer w10: R21.1 R20.2 1084.74,270 U1.17
IO7_UART_TX: TP8.1 U1.21 | length 95.4
  Top Layer w6: U1.21 1175.02,152.98 TP8.1
NetC1_1: C1.1 R1.1 U1.57 Y1.3 | length 552.9
  Top Layer w6: U1.57 1301,651 1335,685 1416,685 1459,728 1459,846 1480,867 R1.1 1544,867 C1.1 1570.32,866 Y1.3
NetC8_1: C8.1 R1.2 U1.56 Y1.1 | length 592.1
  Top Layer w6: U1.56 1316.75,644.75 1342,670 1424,670 1475,721 1475,819 1483,827 R1.2 1544,827 C8.1 1562,845 1628.94,845 Y1.1
NetC32_2: C32.2 R4.1 R5.2 U2.5 | length 155.2
  Top Layer w12: U2.5 1111,813.2 R5.2 C32.2 R4.1
NetL1_1: L1.1 U2.3
RESET_N: C33.2 R6.2 U1.30 | length 167.1
  Top Layer w6: U1.30 1316.75,112.08 R6.2 C33.2
USB5V: 
pads on no net: CON.2 CON.3 CON.4 CON.10 CON.11 J1.13 J2.13 J2.14 U1.22 U1.23 U1.24 U1.28 U1.29 U1.33 U1.34 U1.37 U1.38 U1.39 U1.66

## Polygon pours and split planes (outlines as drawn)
DVDD33 on POW "Power-No Net" (solid, remove dead copper, pour order 0): 1350,637 1328,637 1315,624 1244,624 1244,609 1244,606 1228,590 1146,590 1138,598 1131,605 1131,624 1131,628 1096,628 1086,628 1086,542 1040,496 1040,474 1040,470 1059,451 1065,445 1065,415.39 1063.39,415.39 1035,387 1035,366 1060,341 1063,338 1063,305.65 1056.35,299 1037,299 1025,311 1010,311 1010,269 1071,269 1085,283 1287,283 1301,269 1332,238 1332,171 1344,159 1371,159 1382,170 1382,196 1382,283 1402,303 1418,319 1474,319 1474,343 1467,350 1461,356 1461,386 1461,429 1432,429 1420,429 1420,379 1364,323 1143,323 1110,356 1110,487 1146,523 1158,535 1286,535 1394,535 1394,621 1377,621 1362,606 1349,606 1349,637
DVDD12 on POW "Power-No Net" (solid, remove dead copper, pour order 2): 1427,819 1333,819 1333,692 1310,669 1236,669 1034,669 1034,562 1034,560.81 988,514.81 988,371 967,350 967,231 1075,231 1168,231 1216,183 1289,110 1397,110 1448,161 1448,206 1448,235 1469,256 1480,267 1532,267 1532,347 1504,375 1463,375 1459.39,375 1459.39,351.97 1476,335.35 1476,314 1442,314 1437,309 1391,263 1391,209 1391,168 1375,152 1342,152 1333,161 1318,161 1316,161 1198,279 1089,279 1077,267 1006,267 1006,290 1006,316 1026.5,316 1038.5,304 1051,304 1056,304 1056,331 1028,359 1028,378 1028,387 1048,407 1065,424 1065,445 1031,479 1031,494 1059,522 1081,544 1081,633 1112,633 1135,633 1135,612 1149,598 1207,598 1239,598 1239,617 1239,626 1312,626 1327,641 1353,641 1353,627 1353,611 1363,611 1398,611 1398,592 1398,532 1465,532 1465,553 1441,577 1433,585 1433,625 1433.5,667.5 1397,704 1397,747 1433,783 1433,819
GND on POW "Power-No Net" (solid, remove dead copper, pour order 8): 0,0 0,1000 2460.63,1000 2460.63,862.32 2318.9,862.32 2318.9,137.91 2460.63,137.91 2460.63,0 923.85,0 923.85,98.54 530.15,98.54 530.15,0
GND on GND "Power-No Net" (solid, remove dead copper, pour order 6): 0,0 0,1000 2460.63,1000 2460.63,862.32 2318.9,862.32 2318.9,137.91 2460.63,137.91 2460.63,0 923.85,0 923.85,98.54 530.15,98.54 530.15,0
GND on Top Layer "Power-No Net" (solid, remove dead copper, pour order 12): 0,0 0,1000 2460.63,1000 2460.63,862.32 2318.9,862.32 2318.9,137.91 2460.63,137.91 2460.63,0 923.85,0 923.85,98.54 530.15,98.54 530.15,0
GND on Bottom Layer "Power-No Net" (solid, remove dead copper, pour order 14): 0,0 0,1000 2460.63,1000 2460.63,862.32 2318.9,862.32 2318.9,137.91 2460.63,137.91 2460.63,0 923.85,0 923.85,98.54 530.15,98.54 530.15,0

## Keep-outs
Keep-Out Layer:
  circle w5: c80.32,106.81 r35.43
  circle w5: c2146.85,893.82 r39.37
  circle w5: c80.32,894.21 r35.43
  circle w5: c2146.85,106.42 r39.37
  lines w5: 0,0 0,1000 2460.63,1000 2460.63,862.32 2318.9,862.32 2318.9,137.91 2460.63,137.91 2460.63,0 923.85,0 923.85,98.54 530.15,98.54 530.15,0 0,0

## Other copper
Top Layer:
  region net DVDD12: 1255,830 1329,830 1341,842 1426,842 1426,771 1255,771
  region net NetL1_1: 1315,867 1315,903 1183,903 1183,873 1236,873 1245,864 1315,864
  region net 5V: 1001,771 1064,771 1064,820 1084,840 1133,840 1133,902 1001,902
  region net HDMI_5V: 11,648 11,689 103,689 169,755 277,755 298,776 298,818 396,818 396,717 182,717 113,648
  region net 5V: 357,609 357,649 943,649 1000,706 1000,783 1064,783 1064,771 1044,751 1044,687 966,609
  pour cut-out: 1320.43,880 1320.43,812.57 1245,812.57 1245,880
Bottom Layer:
  region net 5V: 563,712 634,712 668,746 668,831 684,831 684,744 773,655 773,608 635,608 635,631 610,656 563,656
  region net DP_POWER: 2033,206 2033,310 2184,310 2231,357 2321,357 2321,306 2249,306 2203,260 2103,260 2072,229 2072,206
  region net DVDD33: 2002,237 1526,237 1471,182 1382,182 1362,202 1362,224 1328,224 1328,149 1491,149 1543,201 2002,201
  region net DVDD33: 1090,575 1090,787 1140,837 1237,837 1237,787 1157,787 1128,758 1128,575
  region net 5V: 706,678 909,678 976,745 976,843 1012,843 1039,870 1098,870 1098,828 1065,828 1044,807 1044,701 951,608 706,608
  region net DVDD12: 1017,322 1017,347 1088,347 1088,313 1069,313 1059,303 1037,303 1018,322

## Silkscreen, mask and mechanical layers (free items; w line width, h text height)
Mechanical 1:
  circle w5: c2146.85,106.42 r39.37
  circle w5: c80.32,894.21 r35.43
  circle w5: c2146.85,893.82 r39.37
  circle w5: c80.32,106.81 r35.43
  lines w5: 0,0 530.15,0 530.15,98.54 923.85,98.54 923.85,0 2460.63,0 2460.63,137.91 2318.9,137.91 2318.9,862.32 2460.63,862.32 2460.63,1000 0,1000 0,0
Mechanical 5:
  circle w5: c80.32,106.81 r35.43
  circle w5: c2146.85,893.82 r39.37
  circle w5: c80.32,894.21 r35.43
  circle w5: c2146.85,106.42 r39.37
  lines w5: 0,0 0,1000 2460.63,1000 2460.63,862.32 2318.9,862.32 2318.9,137.91 2460.63,137.91 2460.63,0 923.85,0 923.85,98.54 530.15,98.54 530.15,0 0,0

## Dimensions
0,1000 to 2460.63,1000 on Keep-Out Layer
2460.63,1000 to 2460.63,0 on Keep-Out Layer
